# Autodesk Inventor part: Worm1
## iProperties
Created: 2011-05
Part Number: Worm1
Material: Steel, Mild
Document SubType Name: Modeling
Designer: 904Chiaki
Categories: <?xml version="1.0" encoding="UTF-16"?> <MemberInstance><Categories><FamilyTemplate><FamilyTemplateParameter ValueType="xs:double" Id="1" ObjectReferenceKey="da
Density: 7.86 g/cm^3
Author: 904Chiaki
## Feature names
1. Base Body [Extrusion]
2. Chamfer1
3. Chamfer2
4. Tooth
5. Tooth Pattern [Circular Pattern]
6. Left Tooth
7. Left Tooth Pattern [Circular Pattern]
8. Extrusion2
